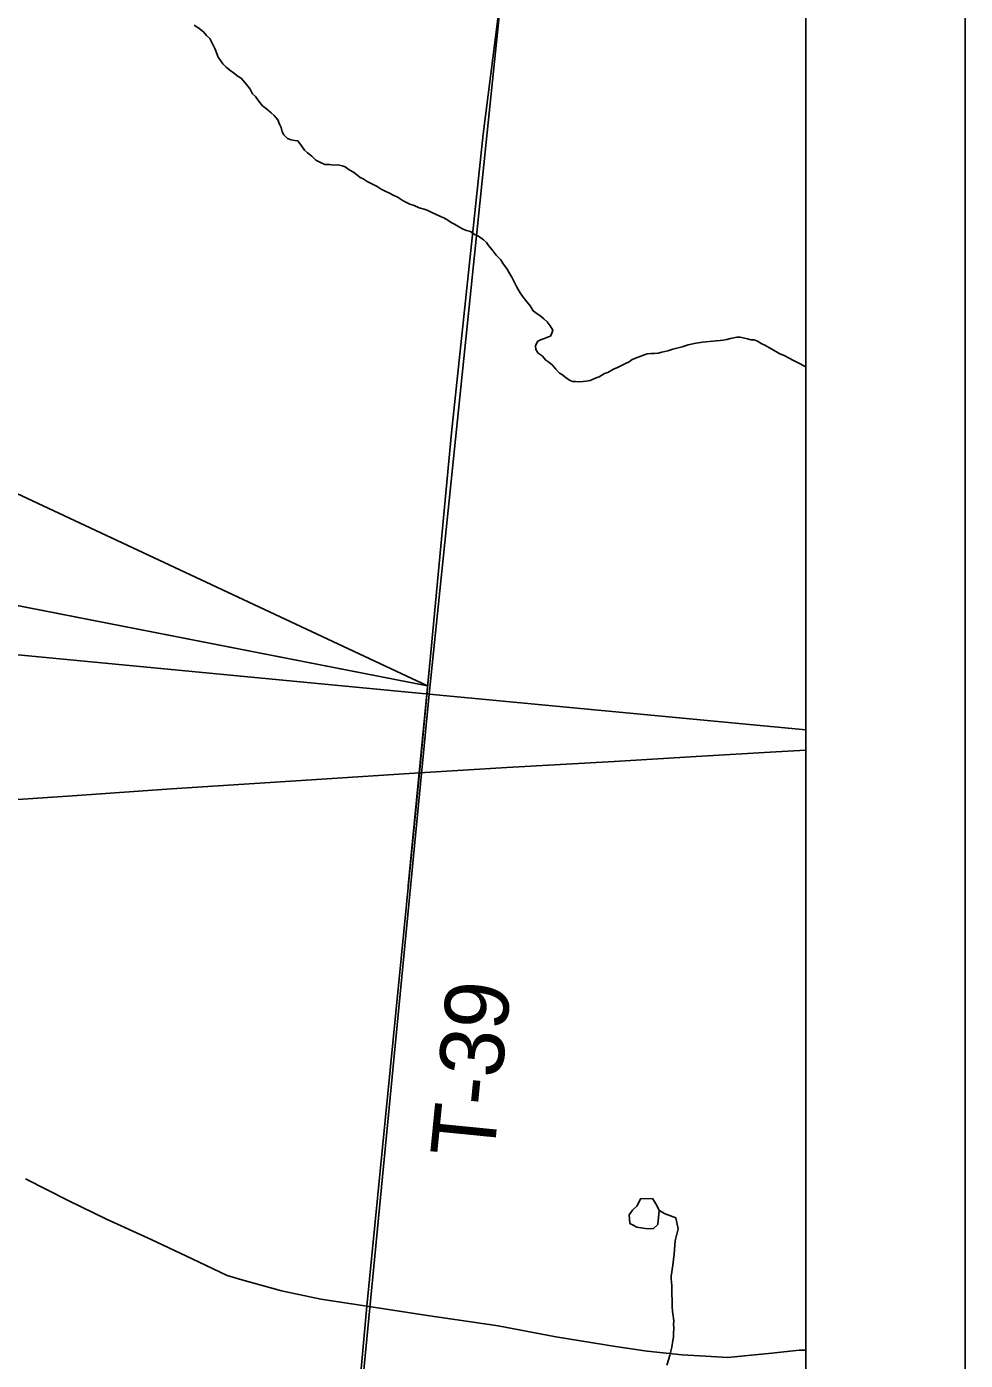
# Model space of a CAD drawing. Extents: x 0 to 34, y -4 to 22.
# Drawn here: x 8.412 to 9, y 19.435 to 20.27 of the extents above; entities that cross this region are included whole.
import ezdxf

# ---------------------------------------------------------------- set-up
doc = ezdxf.new("R2010")
doc.units = 0
for name, color, linetype in [('GM_X_Interstate_Route', 7, 'Continuous'), ('GM_X_Minor_Lake', 7, 'Continuous'), ('GM_X_Minor_River', 7, 'Continuous'), ('GM_X_Section', 7, 'Continuous'), ('GM_X_State_Route', 7, 'Continuous'), ('GM_X_Township_Road', 7, 'Continuous'), ('GM_X_Township_Road_Text', 7, 'Continuous'), ('SH_Data', 7, 'Continuous'), ('SH_Text', 7, 'Continuous'), ('SN_P_Text', 7, 'Continuous'), ('TX_P_100', 7, 'Continuous')]:
    doc.layers.add(name, color=color, linetype=linetype)

msp = doc.modelspace()

# ---------------------------------------------------------------- linework, layer by layer
at = {"layer": 'GM_X_Interstate_Route'}
msp.add_lwpolyline([(8.37507, 19.78414), (8.44078, 19.7885), (8.50276, 19.79294), (8.58403, 19.79801), (8.65806, 19.80297), (8.71277, 19.80624), (8.78009, 19.81003), (8.83132, 19.81312), (8.8812, 19.81597), (8.9, 19.81712)], dxfattribs=at)
at = {"layer": 'GM_X_Minor_Lake'}
for points in [[(8.8083, 19.52876), (8.80651, 19.53229), (8.80393, 19.53636), (8.79642, 19.53601), (8.79444, 19.53177), (8.79143, 19.5289), (8.78948, 19.52601), (8.78989, 19.52064), (8.792, 19.51952), (8.79412, 19.5184)], [(8.79412, 19.5184), (8.79678, 19.5178), (8.79972, 19.51746), (8.80454, 19.51735), (8.80728, 19.51996), (8.8083, 19.52876)]]:
    msp.add_lwpolyline(points, dxfattribs=at)
at = {"layer": 'GM_X_Minor_River'}
for points in [[(8.5169, 20.27117), (8.51926, 20.26976), (8.52266, 20.26698), (8.52473, 20.26478), (8.52681, 20.26284), (8.52781, 20.26068), (8.53007, 20.25606), (8.5308, 20.2539), (8.53205, 20.25119), (8.53332, 20.24902), (8.53485, 20.24683), (8.53693, 20.2449)], [(8.53693, 20.2449), (8.53928, 20.24296), (8.54163, 20.24128), (8.54451, 20.23905), (8.54635, 20.23793), (8.5497, 20.23408), (8.55201, 20.23107), (8.55352, 20.22809), (8.55534, 20.22643), (8.55713, 20.2237), (8.55971, 20.22068), (8.56232, 20.21873), (8.56519, 20.21624), (8.56701, 20.21458), (8.56933, 20.21184), (8.57031, 20.20913), (8.57131, 20.20696), (8.57203, 20.20427), (8.57304, 20.20237), (8.57538, 20.20016), (8.57776, 20.19928), (8.57989, 20.19895), (8.58175, 20.19863), (8.58407, 20.19562), (8.58612, 20.19288), (8.58794, 20.19122), (8.59055, 20.189), (8.59314, 20.18652), (8.59604, 20.18509), (8.59869, 20.18394), (8.6019, 20.18384), (8.60403, 20.18351), (8.60698, 20.18369), (8.60964, 20.18307), (8.6115, 20.18248), (8.61411, 20.18053), (8.61674, 20.17911), (8.61857, 20.17772), (8.62092, 20.17577), (8.62277, 20.17492), (8.62539, 20.17323), (8.62855, 20.17153), (8.63145, 20.17011), (8.63407, 20.16842), (8.63697, 20.167), (8.63882, 20.16614), (8.64198, 20.16444), (8.64409, 20.16357), (8.64776, 20.16105), (8.65198, 20.15905), (8.65463, 20.15817), (8.6578, 20.15673), (8.66098, 20.15583), (8.66284, 20.15524), (8.66574, 20.15382), (8.66759, 20.15296), (8.67128, 20.15124), (8.6734, 20.15038), (8.67576, 20.14897), (8.67786, 20.14757), (8.67996, 20.14643), (8.68312, 20.14473), (8.68549, 20.14332), (8.6876, 20.14246), (8.68999, 20.14185), (8.69288, 20.13989), (8.69499, 20.13902), (8.69813, 20.13679), (8.69995, 20.13513), (8.70123, 20.13322), (8.70355, 20.13047), (8.70612, 20.12719), (8.70897, 20.12416), (8.71049, 20.12171), (8.71255, 20.11898), (8.71457, 20.11544), (8.71584, 20.11326), (8.71761, 20.11), (8.71887, 20.10756), (8.71988, 20.10566), (8.72115, 20.10348), (8.72293, 20.10076), (8.72551, 20.09774), (8.7273, 20.09528), (8.72935, 20.09227), (8.7317, 20.09033), (8.73353, 20.08921), (8.73588, 20.08726), (8.73796, 20.08533), (8.74002, 20.08286), (8.74154, 20.08014), (8.74094, 20.07829), (8.74008, 20.07645), (8.73818, 20.0757), (8.73628, 20.07496), (8.73384, 20.07397), (8.73193, 20.07296), (8.73077, 20.07032), (8.73096, 20.06791), (8.73249, 20.06573), (8.73485, 20.06405)], [(8.73485, 20.06405), (8.73717, 20.06131), (8.73901, 20.06018), (8.74135, 20.05824), (8.74342, 20.05577), (8.74575, 20.05329), (8.74758, 20.05217), (8.74941, 20.05078), (8.75203, 20.04883), (8.75387, 20.04797), (8.75575, 20.04791), (8.75789, 20.04784), (8.76057, 20.04803), (8.76246, 20.04824), (8.76488, 20.0487), (8.76868, 20.05018), (8.77058, 20.05092), (8.77387, 20.05296), (8.77603, 20.0537), (8.77958, 20.05572), (8.78203, 20.05672), (8.7842, 20.05772), (8.7872, 20.05923), (8.78938, 20.06023), (8.7913, 20.06177), (8.7951, 20.06326), (8.79836, 20.06449), (8.80079, 20.06522), (8.80294, 20.06542), (8.80536, 20.06561), (8.80751, 20.06581), (8.80994, 20.06627), (8.81372, 20.06723), (8.8167, 20.0682), (8.82021, 20.06916), (8.82264, 20.06962), (8.82454, 20.07036), (8.82643, 20.07084), (8.82832, 20.07132), (8.83129, 20.07203), (8.83533, 20.0727), (8.83748, 20.0729), (8.84178, 20.07331), (8.84393, 20.07351), (8.84635, 20.0737), (8.84823, 20.07391), (8.85066, 20.07437), (8.85281, 20.07484), (8.85497, 20.0753), (8.85687, 20.07578), (8.85901, 20.07571), (8.86167, 20.0751), (8.86353, 20.07477), (8.86592, 20.07416), (8.86779, 20.07411), (8.86991, 20.07324), (8.87253, 20.07156), (8.87438, 20.0707), (8.87727, 20.069), (8.8799, 20.06759), (8.88174, 20.06646), (8.88385, 20.06533), (8.88649, 20.06418), (8.88965, 20.06248), (8.89228, 20.06106), (8.89413, 20.0602), (8.8965, 20.05906), (8.89834, 20.05794), (8.9, 20.05725)], [(8.81575, 19.48757), (8.81684, 19.49457), (8.81755, 19.50151), (8.81828, 19.50979), (8.82007, 19.51724), (8.81864, 19.52423), (8.81204, 19.52674), (8.8083, 19.52876)], [(8.81311, 19.43196), (8.81431, 19.43593), (8.81491, 19.43805), (8.81554, 19.4407), (8.81615, 19.44309), (8.81683, 19.44734), (8.81717, 19.44947), (8.81724, 19.4516), (8.81736, 19.45534), (8.81716, 19.45748), (8.81749, 19.45934), (8.81729, 19.46122), (8.81684, 19.4639), (8.81663, 19.46578), (8.81644, 19.46819), (8.81627, 19.47087), (8.81634, 19.473), (8.81616, 19.47568), (8.81624, 19.47835), (8.81608, 19.48156), (8.81589, 19.48397), (8.81569, 19.48584), (8.81575, 19.48757)]]:
    msp.add_lwpolyline(points, dxfattribs=at)
at = {"layer": 'GM_X_Section'}
for points in [[(8.0438, 20.5539), (8.73019, 20.4912), (8.66411, 19.85205), (7.97405, 19.91801)], [(8.9, 19.82975), (8.9, 20.47381), (8.73019, 20.4912), (8.66411, 19.85205)], [(7.97405, 19.91801), (8.66411, 19.85205), (8.59171, 19.1029), (7.90105, 19.1654)], [(8.9, 19.07415), (8.9, 19.82975), (8.66411, 19.85205), (8.59171, 19.1029)]]:
    msp.add_lwpolyline(points, close=True, dxfattribs=at)
at = {"layer": 'GM_X_State_Route'}
msp.add_lwpolyline([(8.41133, 19.54848), (8.43806, 19.53501), (8.4619, 19.52323), (8.48998, 19.51054), (8.51568, 19.49844), (8.53767, 19.48803), (8.54671, 19.48542), (8.57172, 19.47842), (8.59624, 19.4733), (8.62507, 19.46888), (8.66162, 19.46322), (8.70727, 19.45654), (8.74353, 19.44955), (8.78088, 19.4436), (8.80063, 19.44073), (8.82254, 19.43835), (8.84073, 19.43739), (8.85116, 19.43661), (8.86378, 19.43792), (8.87881, 19.43945), (8.89599, 19.44119), (8.9, 19.44132)], dxfattribs=at)
at = {"layer": 'GM_X_Township_Road'}
for points in [[(8.62507, 19.46888), (8.65806, 19.80297), (8.67815, 20.01586), (8.69801, 20.20289), (8.73462, 20.49213)], [(8.59311, 19.11604), (8.59311, 19.11604), (8.62507, 19.46888)]]:
    msp.add_lwpolyline(points, dxfattribs=at)
at = {"layer": 'SH_Data'}
for p, q in [((9, 21), (9, 14)), ((8.9, 20.9), (8.9, 14.1)), ((8.65107, 19.73211), (8.66575, 19.88451))]:
    msp.add_line(p, q, dxfattribs=at)
at = {"layer": 'SH_Text'}
msp.add_line((7.8251, 20.0213), (8.66314, 19.85741), dxfattribs=at)
at = {"layer": 'SN_P_Text'}
msp.add_lwpolyline([(8.9, 14.1), (8.9, 20.9), (2.1, 20.9), (2.1, 14.1)], close=True, dxfattribs=at)
at = {"layer": 'TX_P_100'}
msp.add_lwpolyline([(7.8251, 20.0213), (8.66314, 19.85741), (7.8251, 20.24966)], close=True, dxfattribs=at)

# ---------------------------------------------------------------- texts
at = {"layer": 'GM_X_Township_Road_Text'}
msp.add_text('T-39', height=0.04, rotation=84.3598, dxfattribs=at).set_placement((8.70456, 19.56076))

doc.saveas('drawing.dxf')
